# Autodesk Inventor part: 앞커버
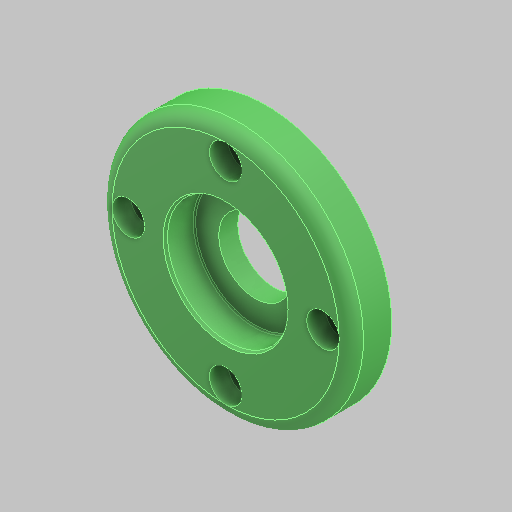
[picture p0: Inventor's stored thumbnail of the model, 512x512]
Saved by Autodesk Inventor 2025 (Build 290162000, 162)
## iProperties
Created: 2024-07
Part Number: 앞커버
Material: 알루미늄 6061
Document SubType Name: Modeling
Designer: 현기
Density: 2.71 g/cm^3
Appearance: 기본값
Author: jhkim
Sending System: Autodesk Inventor 2025
Preprocessor: ST-DEVELOPER v20
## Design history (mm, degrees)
feature "솔리드1"
node "솔리드2"
